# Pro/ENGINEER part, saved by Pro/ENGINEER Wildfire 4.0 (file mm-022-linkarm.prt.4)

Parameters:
  METRIC = "NO"

Other parameters: PITCH, DRILL_DIAMETER, THREAD_DIAMETER, THREADS_PER_INCH, THREAD_DEPTH, THREAD_LENGTH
